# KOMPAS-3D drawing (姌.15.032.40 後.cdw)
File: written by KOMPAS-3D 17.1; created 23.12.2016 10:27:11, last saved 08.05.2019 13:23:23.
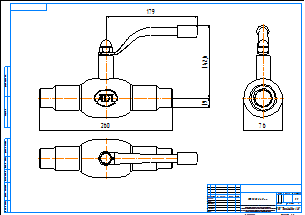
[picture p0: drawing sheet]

Sheet 1: A2, landscape

Title block, sheet 1: name: КШ.15.032.40 сс; material: Внимание! Данный продукт является объектом авторского права ООО «Торговый Дом АДЛ». / Запрещается изменение, копирование, распространение / (в том числе путем копирования на другие сайты и ресурсы в Интернете) / или любое иное использование информации и объектов без предварительного / согласия правообладателя (ООО «Торговый Дом АДЛ»).; sheets: 1; organisation: ООО "Торговый дом АДЛ"; sheet format: A2; stored path: C:\Users\tra\Desktop\2д чертежи\Шаровые краны БИВАЛ\КШ_Бивал_серия_14_15\KOMPAS_2D\КШ.15.032.40 сс.cdw

Views: Вид 1, Проекционный вид 2, Проекционный вид 3
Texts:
  Klimkovich
  ADL
Dimensions and other numbers on the sheet: 260; 179; 142,6; 19; 76; 1:1; 1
